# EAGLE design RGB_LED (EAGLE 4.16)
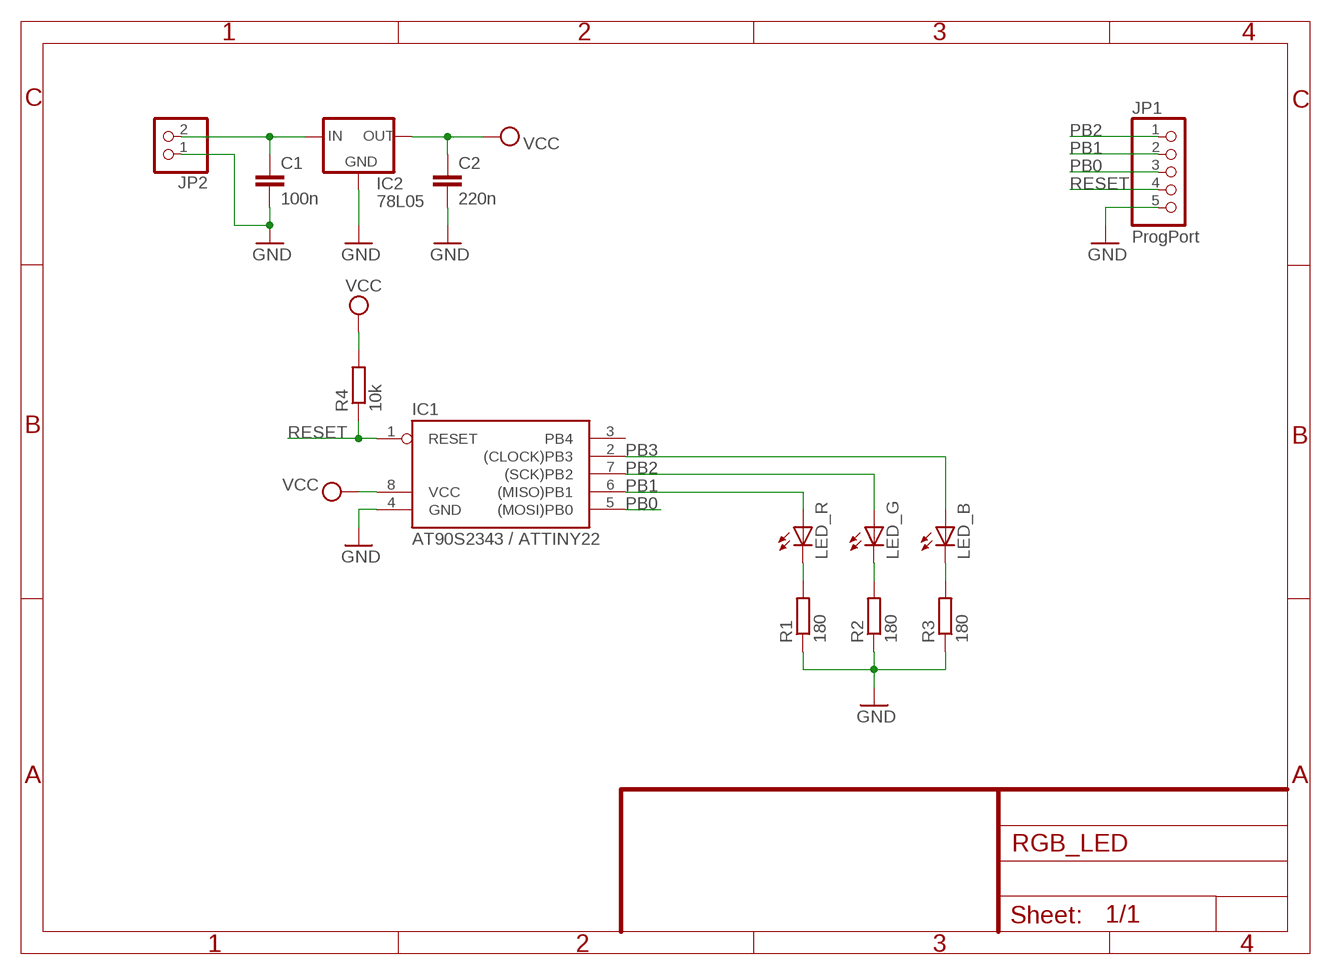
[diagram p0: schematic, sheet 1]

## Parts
C1  100n  C-EUC0805  [C0805]
C2  220n  C-EUC0805  [C0805]
IC1  AT90S2343 / ATTINY22  TINY22S  [SO08]
IC2  78L05  78LXX  [78LXX]
JP1  ProgPort  PINHD-1X5  [1X05]
JP2  PINHD-1X2  [1X02]
LED_B  LED5MM  [LED5MM]
LED_G  LED5MM  [LED5MM]
LED_R  LED5MM  [LED5MM]
R1  180  R-EU_R0603  [R0603]
R2  180  R-EU_R0603  [R0603]
R3  180  R-EU_R0603  [R0603]
R4  10k  R-EU_R0603  [R0603]

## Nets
GND: C1.2 C2.2 IC1.4(GND) IC2.GND JP1.5 JP2.1 R1.1 R2.1 R3.1
N$1: C1.1 IC2.IN JP2.2
N$2: LED_R.K(C) R1.2
N$3: LED_G.K(C) R2.2
N$4: LED_B.K(C) R3.2
PB0: IC1.5((MOSI)PB0) JP1.3
PB1: IC1.6((MISO)PB1) JP1.2 LED_R.A
PB2: IC1.7((SCK)PB2) JP1.1 LED_G.A
PB3: IC1.2((CLOCK)PB3) LED_B.A
RESET: IC1.1(RESET) JP1.4 R4.1
VCC: C2.1 IC1.8(VCC) IC2.OUT R4.2
Unconnected: IC1.3(PB4)

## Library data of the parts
C1 C2 = rcl:C-EU: CAPACITOR, European symbol
IC1 = atmel:TINY22: MICROCONTROLLER 1K ROM 128 bytes RAM 128 bytes EEPROM
IC2 = v-reg:78LXX: VOLTAGE REGULATOR
JP1 = pinhead:PINHD-1X5: PIN HEADER
JP2 = pinhead:PINHD-1X2: PIN HEADER
LED_B LED_G LED_R = led:LED: LED
R1-R4 = rcl:R-EU_: RESISTOR, European symbol

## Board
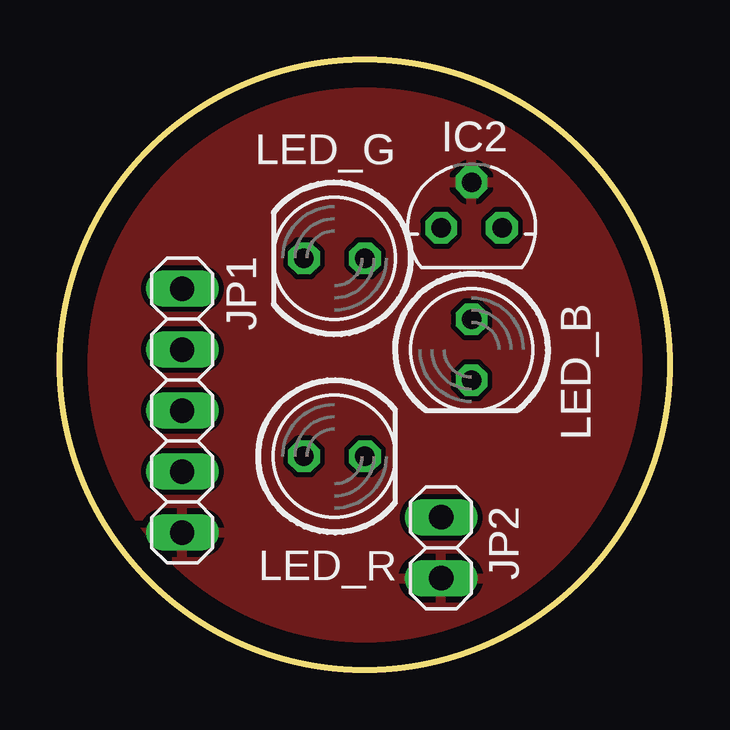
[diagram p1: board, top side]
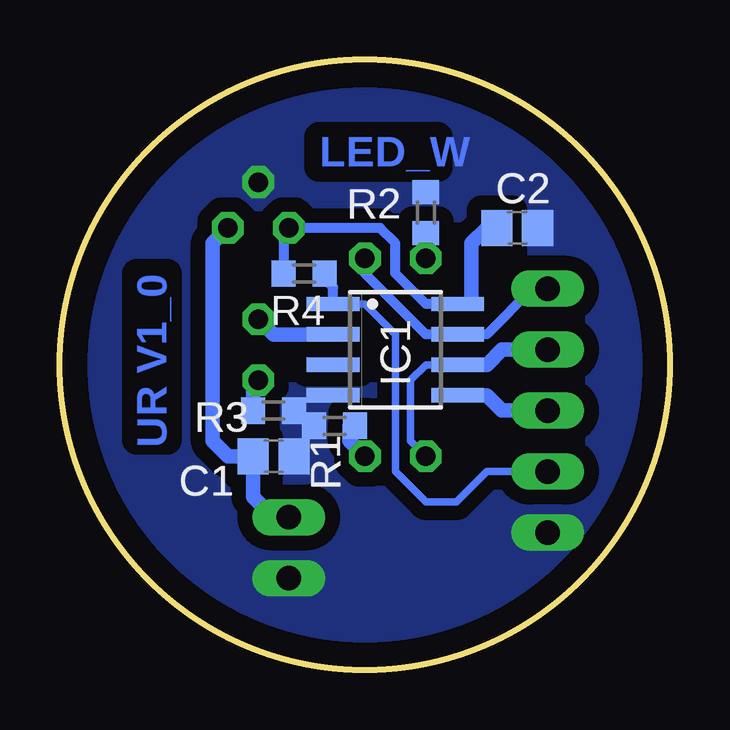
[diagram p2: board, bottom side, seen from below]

Size 25.43 x 25.43 mm. Coordinates in mm from the lower left corner, seen from the top.
Outline: circle at 12.72,12.72 radius 12.72
Copper layers (1*16): Top 0.035mm / dielectric 1.5mm / Bottom 0.035mm
Design rules "default": minimum track width 10mil, minimum drill 24mil, track to track 8mil, track to pad 8mil, pad to pad 8mil, via to via 8mil, smd to smd 8mil, copper to edge 40mil, drill to drill 8mil, minimum pad ring 10mil, minimum via ring 8mil, stop-mask expansion 4mil, vias tented up to drill 0mil, thermal gap 10mil

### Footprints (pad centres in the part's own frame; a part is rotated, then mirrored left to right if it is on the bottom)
C0805 = smd 1.3 x 1.5: 1 -0.85,0; 2 0.85,0
SO08 = smd 0.6 x 2.2: 1 -1.905,-2.6; 2 -0.635,-2.6; 3 0.635,-2.6; 4 1.905,-2.6; 5 1.905,2.6; 6 0.635,2.6; 7 -0.635,2.6; 8 -1.905,2.6
78LXX = drill 0.813 octagon: GND 0,1.905; IN 1.27,0; OUT -1.27,0
1X05 = drill 1.016 long: 1 -5.08,0; 2 -2.54,0; 3 0,0; 4 2.54,0; 5 5.08,0
1X02 = drill 1.016 long: 1 -1.27,0; 2 1.27,0
LED5MM = drill 0.813 octagon: A -1.27,0; K 1.27,0
R0603 = smd 1 x 1.1: 1 -0.85,0; 2 0.85,0

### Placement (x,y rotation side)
C1  16.53,8.91 0 bottom
C2  6.37,18.43 0 bottom
IC1  11.45,13.35 270 bottom
IC2  17.16,18.43 0 top
JP1  5.1,10.81 270 top
JP2  15.89,5.1 90 top
LED_B  17.16,13.35 270 top
LED_G  11.45,17.16 180 top
LED_R  11.45,8.91 0 top
R1  13.99,10.18 0 bottom
R2  10.18,19.07 270 bottom
R3  16.53,10.81 180 bottom
R4  15.26,16.53 180 bottom

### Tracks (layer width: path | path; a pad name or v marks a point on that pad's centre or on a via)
GND
  pour Bottom (isolate 0.61, no thermals): -1.25,26.05 26.05,26.05 26.05,-0.62 -1.25,-0.62
  pour Top: -1.25,26.05 26.05,26.05 26.05,-0.62 -1.25,-0.62
N$1
  Bottom 0.61: JP2.2 16.53,6.37 17.38,7.22 C1.1 18.43,8.91 19.07,9.54 19.07,17.8 IC2.IN
N$2
  Bottom 0.305: 13.35,10.18 R1.2
  Bottom 0.61: 13.35,10.18 13.35,9.54 LED_R.K
N$3
  Bottom 0.406: R2.2 LED_G.K
N$4
  Bottom 0.61: R3.2 17.38,11.87 LED_B.K
PB0
  Bottom 0.406: IC1.5 8.91,11.45
  Bottom 0.61: JP1.3 7,10.81 7.64,11.45 IC1.5
PB1
  Bottom 0.305: 8.91,12.72 10.18,12.72 10.81,12.08 10.81,9.54 LED_R.A
  Bottom 0.406: 8.91,12.72 IC1.6
  Bottom 0.61: JP1.2 7,13.35 7.64,12.72 8.91,12.72
PB2
  Bottom 0.406: JP1.1 5.73,15.89 7.64,13.99 IC1.7 10.18,13.99 12.72,16.53 LED_G.A
PB3
  Bottom 0.61: IC1.2 16.53,13.99 LED_B.A
RESET
  Bottom 0.305: JP1.4 7.64,8.27 8.91,7 10.18,7 11.45,8.27 11.45,13.99 12.72,15.26 IC1.1
  Bottom 0.406: R4.1 14.62,16.53 14.05,15.95 IC1.1
VCC
  Bottom 0.406: 7.64,18.43 C2.1 | 8.27,15.26 IC1.8 10.18,15.26 11.45,16.53 11.45,17.8 12.08,18.43 IC2.OUT 16.11,18.22 R4.2
  Bottom 0.61: 7.64,18.43 8.27,17.8 8.27,15.26

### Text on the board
Bottom: LED_W | UR V1_0
_tNames: LED_G | IC2 | JP1 | LED_B | LED_R | JP2
_bNames: C2 | R2 | IC1 | R3 | R1 | C1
